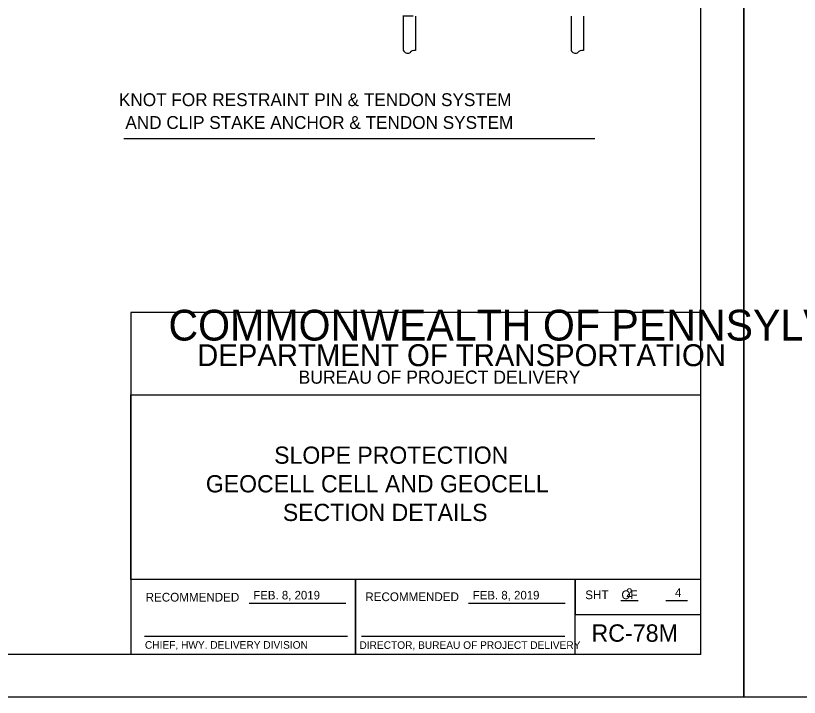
# Model space of a CAD drawing. Extents: x 638850 to 644908, y 297188 to 298900.
# Drawn here: x 639436 to 639710.9, y 297459.5 to 297698.6 of the extents above; entities that cross this region are included whole.
import ezdxf

# ---------------------------------------------------------------- set-up
doc = ezdxf.new("R2010")
doc.units = 0
for name, color, linetype in [('1', 7, 'Continuous'), ('4', 7, 'Continuous'), ('8', 7, 'Continuous'), ('PLT-BNDY', 7, 'Continuous')]:
    doc.layers.add(name, color=color, linetype=linetype)

msp = doc.modelspace()

# ---------------------------------------------------------------- linework, layer by layer
at = {"layer": '1'}
for p, q in [((639676.44, 297474.53), (639676.44, 298038.53)), ((639571.94, 297698.6), (639574.57, 297698.56)), ((639574.85, 297698.56), (639575.42, 297698.59)), ((639676.44, 297594.53), (639476.44, 297594.53)), ((639476.44, 297594.53), (639476.44, 297474.53)), ((639676.44, 297565.57), (639676.44, 297594.53)), ((639476.44, 297500.89), (639476.44, 297565.57)), ((639476.44, 297565.57), (639676.44, 297565.57)), ((639676.44, 297500.89), (639476.44, 297500.89)), ((639555.24, 297474.53), (639555.24, 297500.89)), ((639555.24, 297500.89), (639555.24, 297474.53)), ((639632.24, 297474.53), (639632.24, 297500.89)), ((639632.24, 297500.89), (639632.24, 297488.57)), ((639676.44, 297474.53), (639676.44, 297500.89)), ((639648.3, 297493.5), (639654.45, 297493.5)), ((639664.11, 297493.5), (639671.76, 297493.5)), ((639517.9, 297492.52), (639551.79, 297492.52)), ((639594.9, 297492.52), (639628.77, 297492.52)), ((639632.24, 297488.57), (639676.44, 297488.57)), ((639481.2, 297480.96), (639552.45, 297480.96)), ((639557.37, 297480.96), (639628.71, 297480.96)), ((639676.44, 297474.53), (638890.44, 297474.53))]:
    msp.add_line(p, q, dxfattribs=at)
for centre, start, end in [((639572.02, 297703.6), 267.1952, 269.1043), ((639574.65, 297703.56), 269.1043, 272.2801)]:
    msp.add_arc(centre, 5, start, end, dxfattribs=at)
at = {"layer": '4'}
msp.add_line((639473.96, 297655.54), (639639.21, 297655.54), dxfattribs=at)
at = {"layer": '8'}
for p, q in [((639571.99, 297698.41), (639571.99, 297686.46)), ((639576.31, 297698.41), (639576.31, 297686.37)), ((639630.88, 297698.41), (639630.88, 297686.46)), ((639635.2, 297698.41), (639635.2, 297686.37)), ((639574.23, 297685.59), (639574.23, 297685.59)), ((639629.91, 297685.95), (639629.91, 297685.95)), ((639633.12, 297685.59), (639633.12, 297685.59))]:
    msp.add_line(p, q, dxfattribs=at)
for centre, radius, start, end in [((639573.55, 297687.15), 1.7, 203.8145, 293.8513), ((639575.81, 297684.53), 1.9, 74.7189, 145.9423), ((639632.44, 297687.15), 1.7, 203.8145, 293.8513), ((639634.7, 297684.53), 1.9, 74.7189, 145.9423)]:
    msp.add_arc(centre, radius, start, end, dxfattribs=at)
at = {"layer": 'PLT-BNDY'}
for points in [[(638850.44, 298053.53), (639691.44, 298053.53), (639691.44, 297459.53), (638850.44, 297459.53)], [(639691.44, 298053.53), (640532.44, 298053.53), (640532.44, 297459.53), (639691.44, 297459.53)]]:
    msp.add_lwpolyline(points, close=True, dxfattribs=at)

# ---------------------------------------------------------------- texts
at = {"layer": '1'}
for s, height, p in [('COMMONWEALTH OF PENNSYLVANIA', 10.7834, (639489.59, 297584.67)), ('DEPARTMENT OF TRANSPORTATION', 7.6843, (639499.65, 297575.68)), ('BUREAU OF PROJECT DELIVERY', 4.6221, (639535.23, 297569.52)), ('SLOPE PROTECTION', 6.04, (639526.7, 297541.45)), ('GEOCELL CELL AND GEOCELL', 6.04, (639502.71, 297531.41)), ('SECTION DETAILS', 6.04, (639529.74, 297521.37)), ('RECOMMENDED', 3.048, (639481.6, 297493.12)), ('FEB. 8, 2019', 3, (639519.35, 297493.86)), ('RECOMMENDED', 3.048, (639558.67, 297493.27)), ('FEB. 8, 2019', 3, (639596.35, 297493.86)), ('SHT    OF', 3.048, (639635.84, 297493.96)), ('2', 3.05, (639650.16, 297494.7)), ('4', 3.05, (639667.29, 297494.7)), ('APPROVED', 0.0192, (639519.46, 297492.46)), ('RC-78M', 6.096, (639638.01, 297479.02)), ('CHIEF, HWY. DELIVERY DIVISION', 2.6623, (639481.34, 297476.57)), ('DIRECTOR, BUREAU OF PROJECT DELIVERY', 2.6623, (639556.6, 297476.51))]:
    msp.add_text(s, height=height, dxfattribs=at).set_placement(p)
at = {"layer": '4'}
for s, p in [('KNOT FOR RESTRAINT PIN & TENDON SYSTEM', (639472.23, 297666.89)), ('AND CLIP STAKE ANCHOR & TENDON SYSTEM', (639474.48, 297658.89))]:
    msp.add_text(s, height=4.5, dxfattribs=at).set_placement(p)

doc.saveas('drawing.dxf')
